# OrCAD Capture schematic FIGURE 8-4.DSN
size A
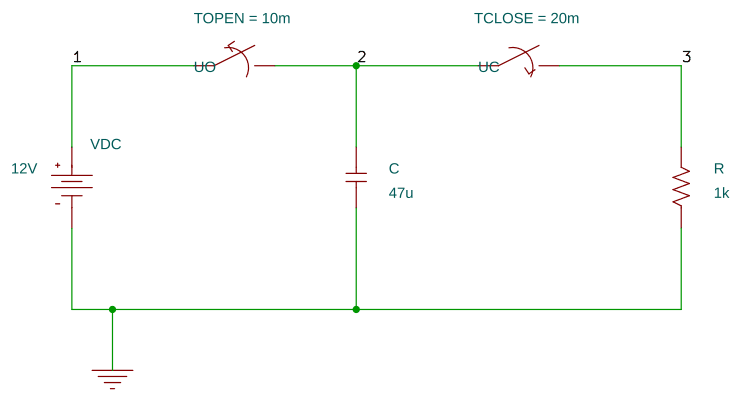
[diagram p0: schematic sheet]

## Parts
C  47u  [RAD/CK05]
R  1k  [AX/RC05]
UC  Sw_tClose
UO  Sw_tOpen
VDC  VDC

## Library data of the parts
C = C
R = R
UC = Sw_tClose: TCLOSE: 20m
UO = Sw_tOpen: TOPEN: 10m
VDC = VDC: DC: 12V

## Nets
0: C.1 R.1 VDC.1(-)
1: UO.1 VDC.0(+)
2: C.2 UC.1 UO.2
3: R.2 UC.2
